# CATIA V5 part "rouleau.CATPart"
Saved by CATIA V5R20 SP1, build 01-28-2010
Part number: rouleau
Bounding box of the stored display mesh (mm): x 0 to 4, y 77.5 to 82.5, z 27.5 to 32.5
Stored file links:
  E:\EDELI\gcausse\Edeli_2012_613_gcausse\rouleau.CATPart
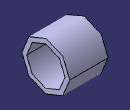
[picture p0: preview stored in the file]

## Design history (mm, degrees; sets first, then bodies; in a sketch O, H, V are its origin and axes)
Body1 (main body)
  Sketch1 on yz-plane, origin (0, 0, 0), H (0, 1, 0), V (0, 0, 1)
    circle A1 centre (80, 30) radius 2
    circle A2 centre (80, 30) radius 2.5
    radius A2 = 2.5
    radius A1 = 2
  Pad1: profile Sketch1, direction (1, 0, 0), length 4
